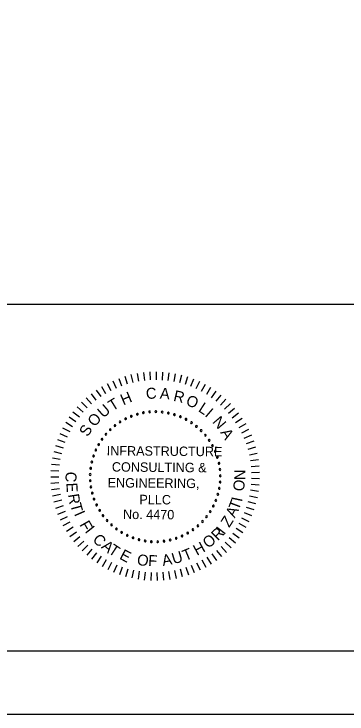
# Model space of a CAD drawing. Extents: x -121.2 to -24.9, y 6.4 to 65.6.
# Drawn here: x -53.92 to -46.89, y 6.35 to 21.15 of the extents above; entities that cross this region are included whole.
import ezdxf

# ---------------------------------------------------------------- set-up
doc = ezdxf.new("R2010")
doc.units = 0
for name, color, linetype in [('BR_BORDER LINES', 7, 'Continuous'), ('BR_TEXT', 7, 'Continuous'), ('Level 31', 7, 'Continuous')]:
    doc.layers.add(name, color=color, linetype=linetype)

msp = doc.modelspace()

# ---------------------------------------------------------------- linework, layer by layer
at = {"layer": 'BR_BORDER LINES'}
for p, q in [((-60.804, 15.017), (-46.496, 15.017)), ((-116.272, 7.683), (-26.496, 7.683))]:
    msp.add_line(p, q, dxfattribs=at)
at = {"layer": 'BR_TEXT'}
for p, q in [((-51.583, 13.49), (-51.533, 13.328)), ((-51.453, 13.526), (-51.413, 13.36)), ((-51.321, 13.553), (-51.292, 13.386)), ((-51.188, 13.572), (-51.169, 13.403)), ((-51.054, 13.583), (-51.045, 13.413)), ((-50.919, 13.586), (-50.921, 13.416)), ((-50.785, 13.58), (-50.796, 13.411)), ((-50.651, 13.567), (-50.673, 13.399)), ((-50.518, 13.545), (-50.55, 13.378)), ((-50.387, 13.515), (-50.429, 13.351)), ((-50.257, 13.478), (-50.31, 13.316)), ((-51.957, 13.338), (-51.878, 13.187)), ((-51.835, 13.396), (-51.766, 13.241)), ((-51.711, 13.447), (-51.651, 13.288)), ((-50.131, 13.432), (-50.193, 13.274)), ((-50.007, 13.379), (-50.079, 13.225)), ((-52.187, 13.2), (-52.091, 13.06)), ((-52.074, 13.272), (-51.987, 13.127)), ((-49.887, 13.318), (-49.968, 13.169)), ((-49.77, 13.251), (-49.86, 13.106)), ((-49.659, 13.176), (-49.757, 13.037)), ((-52.4, 13.034), (-52.287, 12.907)), ((-52.296, 13.12), (-52.192, 12.986)), ((-49.551, 13.094), (-49.658, 12.962)), ((-52.498, 12.942), (-52.378, 12.822)), ((-49.449, 13.006), (-49.564, 12.881)), ((-49.353, 12.913), (-49.475, 12.794)), ((-52.677, 12.741), (-52.543, 12.636)), ((-52.59, 12.844), (-52.463, 12.732)), ((-49.262, 12.813), (-49.391, 12.702)), ((-52.757, 12.633), (-52.617, 12.536)), ((-49.178, 12.708), (-49.313, 12.606)), ((-49.1, 12.598), (-49.242, 12.504)), ((-52.83, 12.52), (-52.684, 12.432)), ((-49.029, 12.484), (-49.176, 12.398)), ((-52.896, 12.402), (-52.745, 12.324)), ((-48.966, 12.365), (-49.117, 12.289)), ((-53.006, 12.157), (-52.847, 12.097)), ((-52.954, 12.281), (-52.799, 12.212)), ((-48.909, 12.243), (-49.065, 12.176)), ((-53.049, 12.029), (-52.887, 11.98)), ((-48.86, 12.117), (-49.02, 12.06)), ((-48.819, 11.989), (-48.982, 11.942)), ((-53.085, 11.9), (-52.92, 11.86)), ((-48.786, 11.859), (-48.951, 11.822)), ((-53.113, 11.768), (-52.946, 11.738)), ((-48.76, 11.727), (-48.928, 11.7)), ((-53.132, 11.635), (-52.964, 11.615)), ((-48.743, 11.593), (-48.912, 11.576)), ((-53.144, 11.501), (-52.974, 11.491)), ((-48.734, 11.459), (-48.904, 11.452)), ((-53.147, 11.366), (-52.978, 11.367)), ((-48.734, 11.324), (-48.903, 11.328)), ((-53.142, 11.231), (-52.973, 11.243)), ((-53.129, 11.097), (-52.961, 11.119)), ((-48.741, 11.19), (-48.91, 11.204)), ((-53.108, 10.965), (-52.941, 10.997)), ((-48.78, 10.923), (-48.947, 10.958)), ((-48.757, 11.056), (-48.925, 11.081)), ((-53.079, 10.833), (-52.914, 10.875)), ((-48.812, 10.793), (-48.976, 10.838)), ((-53.042, 10.704), (-52.88, 10.756)), ((-48.852, 10.664), (-49.013, 10.719)), ((-52.997, 10.577), (-52.838, 10.639)), ((-52.944, 10.453), (-52.79, 10.524)), ((-48.899, 10.538), (-49.056, 10.603)), ((-52.884, 10.333), (-52.734, 10.413)), ((-49.017, 10.296), (-49.165, 10.379)), ((-48.954, 10.415), (-49.107, 10.489)), ((-52.816, 10.216), (-52.672, 10.306)), ((-49.086, 10.181), (-49.229, 10.273)), ((-52.742, 10.104), (-52.603, 10.202)), ((-52.661, 9.996), (-52.529, 10.103)), ((-49.246, 9.964), (-49.376, 10.073)), ((-49.163, 10.07), (-49.3, 10.17)), ((-52.573, 9.894), (-52.448, 10.008)), ((-52.48, 9.797), (-52.362, 9.919)), ((-49.335, 9.863), (-49.459, 9.98)), ((-52.381, 9.706), (-52.27, 9.835)), ((-49.532, 9.679), (-49.64, 9.81)), ((-49.431, 9.768), (-49.547, 9.892)), ((-52.276, 9.622), (-52.173, 9.757)), ((-52.166, 9.543), (-52.072, 9.685)), ((-49.749, 9.521), (-49.841, 9.663)), ((-49.638, 9.597), (-49.738, 9.734)), ((-52.052, 9.472), (-51.967, 9.619)), ((-51.934, 9.408), (-51.858, 9.56)), ((-51.812, 9.351), (-51.745, 9.507)), ((-50.107, 9.335), (-50.171, 9.492)), ((-49.984, 9.389), (-50.058, 9.542)), ((-49.864, 9.451), (-49.947, 9.6)), ((-51.687, 9.302), (-51.629, 9.461)), ((-51.559, 9.26), (-51.511, 9.423)), ((-51.428, 9.226), (-51.391, 9.392)), ((-51.296, 9.2), (-51.269, 9.368)), ((-51.163, 9.183), (-51.146, 9.352)), ((-51.028, 9.173), (-51.022, 9.343)), ((-50.894, 9.172), (-50.898, 9.342)), ((-50.759, 9.179), (-50.773, 9.348)), ((-50.626, 9.194), (-50.65, 9.362)), ((-50.493, 9.217), (-50.528, 9.384)), ((-50.362, 9.249), (-50.407, 9.412)), ((-50.233, 9.288), (-50.288, 9.449))]:
    msp.add_line(p, q, dxfattribs=at)
for centre, start, end in [((-51.19, 12.72), 10.6038, 190.6038), ((-51.058, 12.738), 5.0653, 185.0653), ((-51.058, 12.738), 185.0653, 5.0653), ((-50.926, 12.743), 359.5268, 179.5268), ((-50.926, 12.743), 179.5268, 359.5268), ((-50.793, 12.735), 353.9884, 173.9884), ((-50.793, 12.735), 173.9884, 353.9884), ((-50.662, 12.714), 348.4499, 168.4499), ((-51.566, 12.592), 27.2191, 207.2191), ((-51.566, 12.592), 207.2191, 27.2191), ((-51.445, 12.647), 21.6807, 201.6807), ((-51.445, 12.647), 201.6807, 21.6807), ((-51.319, 12.689), 16.1422, 196.1422), ((-51.319, 12.689), 196.1422, 16.1422), ((-51.19, 12.72), 190.6038, 10.6038), ((-50.662, 12.714), 168.4499, 348.4499), ((-50.533, 12.681), 162.9114, 342.9114), ((-50.533, 12.681), 342.9114, 162.9114), ((-50.408, 12.636), 157.373, 337.373), ((-50.408, 12.636), 337.373, 157.373), ((-50.288, 12.579), 151.8345, 331.8345), ((-50.288, 12.579), 331.8345, 151.8345), ((-51.79, 12.449), 38.2961, 218.2961), ((-51.79, 12.449), 218.2961, 38.2961), ((-51.682, 12.526), 32.7576, 212.7576), ((-51.682, 12.526), 212.7576, 32.7576), ((-50.174, 12.51), 146.2961, 326.2961), ((-50.174, 12.51), 326.2961, 146.2961), ((-50.068, 12.431), 140.7576, 320.7576), ((-50.068, 12.431), 320.7576, 140.7576), ((-51.89, 12.362), 43.8345, 223.8345), ((-51.89, 12.362), 223.8345, 43.8345), ((-49.969, 12.342), 135.2191, 315.2191), ((-49.969, 12.342), 315.2191, 135.2191), ((-52.063, 12.16), 54.9114, 234.9114), ((-52.063, 12.16), 234.9114, 54.9114), ((-51.982, 12.265), 49.373, 229.373), ((-51.982, 12.265), 229.373, 49.373), ((-49.88, 12.244), 129.6807, 309.6807), ((-49.88, 12.244), 309.6807, 129.6807), ((-49.8, 12.137), 124.1422, 304.1422), ((-49.8, 12.137), 304.1422, 124.1422), ((-52.135, 12.048), 60.4499, 240.4499), ((-52.135, 12.048), 240.4499, 60.4499), ((-49.731, 12.024), 118.6038, 298.6038), ((-49.731, 12.024), 298.6038, 118.6038), ((-52.195, 11.93), 65.9884, 245.9884), ((-52.195, 11.93), 245.9884, 65.9884), ((-49.673, 11.904), 113.0653, 293.0653), ((-49.673, 11.904), 293.0653, 113.0653), ((-52.279, 11.678), 77.0653, 257.0653), ((-52.279, 11.678), 257.0653, 77.0653), ((-52.243, 11.806), 71.5268, 251.5268), ((-52.243, 11.806), 251.5268, 71.5268), ((-49.628, 11.779), 107.5268, 287.5268), ((-49.628, 11.779), 287.5268, 107.5268), ((-52.303, 11.547), 82.6038, 262.6038), ((-52.303, 11.547), 262.6038, 82.6038), ((-49.594, 11.651), 101.9884, 281.9884), ((-49.594, 11.651), 281.9884, 101.9884), ((-52.314, 11.415), 88.1422, 268.1422), ((-52.314, 11.415), 268.1422, 88.1422), ((-49.573, 11.519), 96.4499, 276.4499), ((-49.565, 11.387), 90.9114, 270.9114), ((-49.573, 11.519), 276.4499, 96.4499), ((-49.565, 11.387), 270.9114, 90.9114), ((-52.312, 11.282), 93.6807, 273.6807), ((-52.312, 11.282), 273.6807, 93.6807), ((-49.569, 11.254), 85.373, 265.373), ((-49.569, 11.254), 265.373, 85.373), ((-52.298, 11.15), 99.2191, 279.2191), ((-52.298, 11.15), 279.2191, 99.2191), ((-49.587, 11.122), 79.8345, 259.8345), ((-49.587, 11.122), 259.8345, 79.8345), ((-52.27, 11.02), 104.7576, 284.7576), ((-52.27, 11.02), 284.7576, 104.7576), ((-49.617, 10.993), 74.2961, 254.2961), ((-49.617, 10.993), 254.2961, 74.2961), ((-52.231, 10.893), 110.2961, 290.2961), ((-52.231, 10.893), 290.2961, 110.2961), ((-49.659, 10.867), 68.7576, 248.7576), ((-49.659, 10.867), 248.7576, 68.7576), ((-52.179, 10.771), 115.8345, 295.8345), ((-52.179, 10.771), 295.8345, 115.8345), ((-52.115, 10.654), 121.373, 301.373), ((-52.115, 10.654), 301.373, 121.373), ((-49.713, 10.746), 63.2191, 243.2191), ((-49.713, 10.746), 243.2191, 63.2191), ((-52.041, 10.544), 126.9114, 306.9114), ((-52.041, 10.544), 306.9114, 126.9114), ((-49.856, 10.522), 52.1422, 232.1422), ((-49.856, 10.522), 232.1422, 52.1422), ((-49.779, 10.63), 57.6807, 237.6807), ((-49.779, 10.63), 237.6807, 57.6807), ((-51.956, 10.441), 132.4499, 312.4499), ((-51.956, 10.441), 312.4499, 132.4499), ((-51.862, 10.348), 317.9884, 137.9884), ((-49.942, 10.421), 46.6038, 226.6038), ((-49.942, 10.421), 226.6038, 46.6038), ((-51.862, 10.348), 137.9884, 317.9884), ((-51.759, 10.263), 143.5268, 323.5268), ((-51.759, 10.263), 323.5268, 143.5268), ((-50.143, 10.247), 35.5268, 215.5268), ((-50.143, 10.247), 215.5268, 35.5268), ((-50.038, 10.329), 41.0653, 221.0653), ((-50.038, 10.329), 221.0653, 41.0653), ((-51.649, 10.189), 149.0653, 329.0653), ((-51.649, 10.189), 329.0653, 149.0653), ((-51.532, 10.126), 154.6038, 334.6038), ((-51.532, 10.126), 334.6038, 154.6038), ((-51.409, 10.075), 160.1422, 340.1422), ((-51.409, 10.075), 340.1422, 160.1422), ((-50.497, 10.066), 18.9114, 198.9114), ((-50.497, 10.066), 198.9114, 18.9114), ((-50.373, 10.115), 24.4499, 204.4499), ((-50.373, 10.115), 204.4499, 24.4499), ((-50.255, 10.175), 29.9884, 209.9884), ((-50.255, 10.175), 209.9884, 29.9884), ((-51.283, 10.036), 345.6807, 165.6807), ((-51.283, 10.036), 165.6807, 345.6807), ((-51.152, 10.009), 351.2191, 171.2191), ((-51.152, 10.009), 171.2191, 351.2191), ((-51.02, 9.995), 356.7576, 176.7576), ((-51.02, 9.995), 176.7576, 356.7576), ((-50.887, 9.993), 2.2961, 182.2961), ((-50.887, 9.993), 182.2961, 2.2961), ((-50.755, 10.005), 7.8345, 187.8345), ((-50.755, 10.005), 187.8345, 7.8345), ((-50.624, 10.029), 13.373, 193.373), ((-50.624, 10.029), 193.373, 13.373)]:
    msp.add_arc(centre, 0.0187, start, end, dxfattribs=at)
at = {"layer": 'Level 31'}
msp.add_lwpolyline([(-121.161, 6.35), (-25.161, 6.35), (-25.161, 65.017), (-121.161, 65.017)], close=True, dxfattribs=at)

# ---------------------------------------------------------------- texts
at = {"layer": 'BR_TEXT'}
for s, height, rotation, p in [('C', 0.233, 4.7281, (-51.127, 13.006)), ('A', 0.233, 355.6981, (-50.848, 13.019)), ('R', 0.233, 346.6681, (-50.57, 12.974)), ('T', 0.233, 31.8182, (-51.841, 12.747)), ('H', 0.233, 22.7882, (-51.615, 12.874)), ('O', 0.233, 337.638, (-50.31, 12.894)), ('U', 0.233, 40.8482, (-52.036, 12.597)), ('L', 0.233, 327.108, (-50.046, 12.759)), ('I', 0.233, 319.578, (-49.906, 12.659)), ('O', 0.233, 49.8782, (-52.215, 12.408)), ('N', 0.233, 310.548, (-49.744, 12.523)), ('S', 0.233, 58.9083, (-52.363, 12.199)), ('A', 0.233, 301.5179, (-49.57, 12.303)), ('INFRASTRUCTURE', 0.19939, 359.5268, (-51.966, 11.819)), ('CONSULTING &', 0.19939, 359.5268, (-51.856, 11.476)), ('C', 0.233, 267.025, (-52.829, 11.479)), ('N', 0.233, 89.2085, (-49.039, 11.293)), ('ENGINEERING,', 0.19939, 359.5268, (-51.946, 11.142)), ('O', 0.233, 83.2085, (-49.068, 11.05)), ('E', 0.233, 273.025, (-52.818, 11.235)), ('R', 0.233, 279.025, (-52.784, 10.989)), ('PLLC', 0.1994, 359.5268, (-51.275, 10.786)), ('T', 0.233, 285.025, (-52.737, 10.779)), ('T', 0.233, 69.3954, (-49.178, 10.645)), ('I', 0.233, 77.9093, (-49.11, 10.825)), ('No. 4470', 0.1994, 359.5268, (-51.62, 10.474)), ('A', 0.233, 63.3954, (-49.26, 10.484)), ('I', 0.233, 293.7713, (-52.658, 10.584)), ('Z', 0.233, 57.3954, (-49.377, 10.28)), ('F', 0.233, 299.7713, (-52.548, 10.355)), ('I', 0.233, 308.5268, (-52.436, 10.211)), ('R', 0.233, 44.5268, (-49.619, 10)), ('I', 0.233, 52.3339, (-49.487, 10.127)), ('C', 0.233, 314.5268, (-52.278, 10.024)), ('O', 0.233, 38.5268, (-49.823, 9.841)), ('A', 0.233, 320.5268, (-52.093, 9.868)), ('T', 0.233, 326.5268, (-51.948, 9.765)), ('H', 0.233, 28.5268, (-50.058, 9.691)), ('E', 0.233, 332.5268, (-51.712, 9.638)), ('U', 0.233, 16.5268, (-50.551, 9.515)), ('T', 0.233, 22.5268, (-50.306, 9.58)), ('O', 0.233, 350.5268, (-51.338, 9.508)), ('F', 0.233, 356.5268, (-51.094, 9.483)), ('A', 0.233, 10.5268, (-50.775, 9.479))]:
    msp.add_text(s, height=height, rotation=rotation, dxfattribs=at).set_placement(p)

doc.saveas('drawing.dxf')
